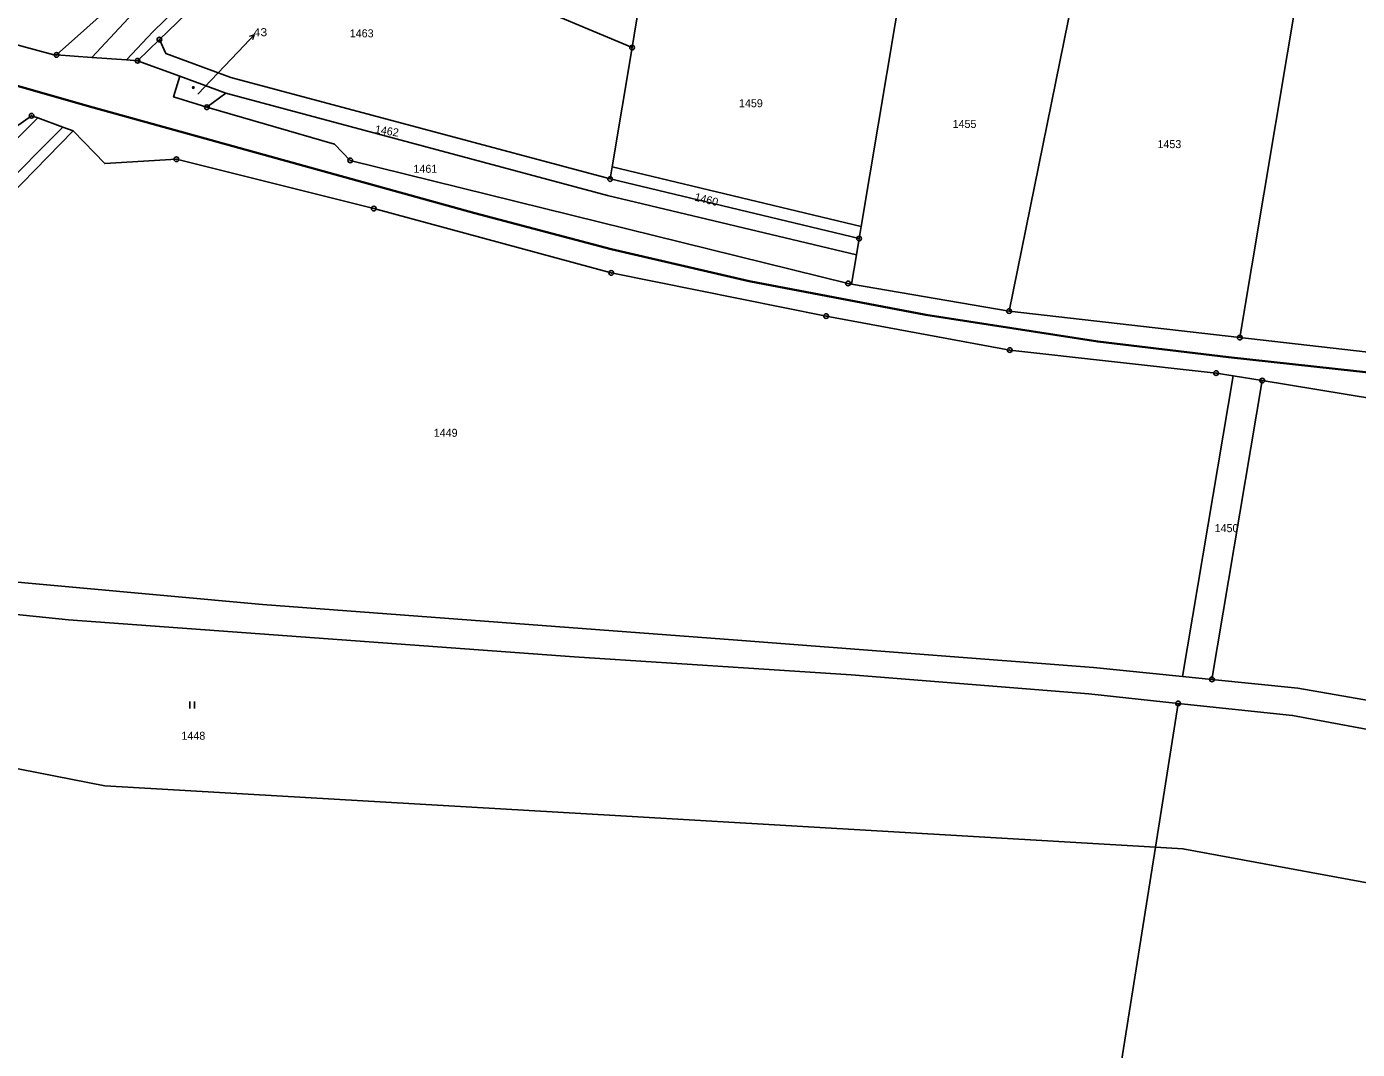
# Model space of a CAD drawing. Extents: x -872229 to -869198, y -1075981 to -1074329.
# Drawn here: x -871207 to -870924.3, y -1075586.7 to -1075369.5 of the extents above; entities that cross this region are included whole.
import ezdxf
from ezdxf.enums import TextEntityAlignment as Align

# ---------------------------------------------------------------- set-up
doc = ezdxf.new("R2010")
doc.units = 0
doc.header["$LTSCALE"] = 0.68
for name, color, linetype, lineweight in [('1', 7, 'Continuous', 25), ('3', 7, 'Continuous', 25), ('4', 7, 'Continuous', 13), ('5', 7, 'Continuous', 25), ('6', 7, 'Continuous', 25), ('7', 7, 'Continuous', 13), ('8', 7, 'Continuous', 25)]:
    doc.layers.add(name, color=color, linetype=linetype, lineweight=lineweight)
doc.layers.add('2', color=7, linetype='Continuous')

msp = doc.modelspace()

# ---------------------------------------------------------------- linework, layer by layer
at = {"layer": '1'}
for p, q in [((-871149.52, -1075343.97), (-871178.79, -1075372.22)), ((-871078.37, -1075373.89), (-871149.52, -1075343.97)), ((-871183.42, -1075376.69), (-871174.48, -1075379.98))]:
    msp.add_line(p, q, dxfattribs=at)
for points in [[(-871146.74, -1075326.85), (-871149.26, -1075329.47), (-871152.59, -1075332.45), (-871180.67, -1075357.59), (-871200.62, -1075375.46)], [(-870928.54, -1075345.19), (-870929.33, -1075345.1), (-870934.07, -1075344.52), (-870949.31, -1075435.5)], [(-871074.84, -1075352.78), (-871077.5, -1075368.64), (-871078.37, -1075373.89), (-871082.62, -1075399.25), (-871029.72, -1075411.9)], [(-870984.86, -1075363.6), (-871020.66, -1075357.83), (-871029.72, -1075411.9), (-871030.15, -1075414.48), (-871030.73, -1075417.93), (-871031.77, -1075424.14), (-870998.3, -1075429.88)], [(-871243.8, -1075363.33), (-871207.98, -1075373.63), (-871201.2, -1075375.48), (-871200.62, -1075375.46)], [(-870984.86, -1075363.6), (-870998.3, -1075429.88), (-870949.31, -1075435.5)], [(-871083.05, -1075401.82), (-871163.59, -1075380.25), (-871177.43, -1075375.17), (-871178.79, -1075372.22), (-871183.42, -1075376.69)], [(-871200.62, -1075375.46), (-871193.17, -1075376.03), (-871185.81, -1075376.53), (-871183.42, -1075376.69)], [(-871030.73, -1075417.93), (-871083.63, -1075405.29), (-871164.66, -1075383.59)], [(-871168.71, -1075386.58), (-871141.62, -1075394.43), (-871138.24, -1075397.87), (-871032.51, -1075424.01), (-871031.77, -1075424.14)], [(-871197.08, -1075391.62), (-871199.28, -1075390.81), (-871204.62, -1075388.86), (-871205.94, -1075388.38), (-871212.24, -1075392.84)], [(-871197.08, -1075391.62), (-871246.11, -1075441.8), (-871278.54, -1075475.47)], [(-870950.68, -1075443.64), (-870954.33, -1075443.04), (-870998.17, -1075438.16), (-871037.17, -1075430.94), (-871082.81, -1075421.77), (-871133.25, -1075408.1), (-871175.19, -1075397.63), (-871190.41, -1075398.53), (-871197.08, -1075391.62)], [(-871082.62, -1075399.25), (-871083.05, -1075401.82), (-871030.15, -1075414.48)], [(-870949.31, -1075435.5), (-870912.76, -1075439.69), (-870824.05, -1075448.17), (-870816.69, -1075448.69), (-870813.04, -1075448.95), (-870783.54, -1075451.03), (-870689.55, -1075462.28), (-870596.02, -1075472.9), (-870575.95, -1075474.7)], [(-871278.54, -1075475.47), (-871235.98, -1075483.88), (-871218.31, -1075486.6), (-871156.9, -1075492.22), (-871055.97, -1075499.77), (-870980.4, -1075505.56), (-870961.43, -1075507.47), (-870950.68, -1075443.64)], [(-870961.43, -1075507.47), (-870955.2, -1075508.1), (-870944.51, -1075444.65), (-870950.68, -1075443.64)], [(-870817.87, -1075462.75), (-870872.87, -1075452.61), (-870914.84, -1075449.51), (-870944.51, -1075444.65)], [(-870962.39, -1075513.2), (-870981.34, -1075511.21), (-871031.87, -1075507.16), (-871090.68, -1075503.32), (-871198.07, -1075495.44), (-871222.24, -1075493), (-871248.51, -1075487.96), (-871283.35, -1075480.46)], [(-870967.23, -1075543.73), (-871082, -1075537.03), (-871190.36, -1075530.7), (-871309.29, -1075507.4)], [(-870955.2, -1075508.1), (-870936.99, -1075509.94), (-870905.68, -1075515.44), (-870845.51, -1075527.2), (-870825.33, -1075530.87)], [(-870769.48, -1075546.88), (-870771.86, -1075546.41), (-870820.28, -1075537.54), (-870823.66, -1075536.9), (-870849.48, -1075531.79), (-870906.42, -1075521.68), (-870938.07, -1075515.76), (-870962.39, -1075513.2), (-870967.23, -1075543.73)], [(-870967.23, -1075543.73), (-870990.41, -1075689.92), (-871013.78, -1075837.33)], [(-870775.56, -1075578.36), (-870961.39, -1075544.07), (-870967.23, -1075543.73)]]:
    msp.add_lwpolyline(points, dxfattribs=at)
msp.add_lwpolyline([(-871174.48, -1075379.98), (-871175.76, -1075384.38), (-871168.71, -1075386.58), (-871164.66, -1075383.59)], close=True, dxfattribs=at)
at = {"layer": '3'}
for p, q in [((-871172.351, -1075514.29), (-871172.351, -1075512.79)), ((-871171.35, -1075514.29), (-871171.35, -1075512.79))]:
    msp.add_line(p, q, dxfattribs=at)
at = {"layer": '4'}
for p, q in [((-871180.16, -1075370.54), (-871118.25, -1075310.04)), ((-871185.81, -1075376.53), (-871180.16, -1075370.54)), ((-871199.28, -1075390.81), (-871239.07, -1075430.66))]:
    msp.add_line(p, q, dxfattribs=at)
for points in [[(-871144.78, -1075328.38), (-871161.44, -1075344.27), (-871180.53, -1075362.44), (-871193.17, -1075376.03)], [(-871326.72, -1075514.76), (-871291.4, -1075477.73), (-871251.44, -1075435.93), (-871204.62, -1075388.86)]]:
    msp.add_lwpolyline(points, dxfattribs=at)
at = {"layer": '5'}
msp.add_circle((-871171.5668, -1075382.3992), 0.175, dxfattribs=at)
at = {"layer": '6', "lineweight": 35}
for p, q in [((-871192.83, -1075386.61), (-871111.78, -1075409.09)), ((-871053.48, -1075423.53), (-871015.95, -1075430.68))]:
    msp.add_line(p, q, dxfattribs=at)
for points in [[(-871283.38, -1075360.82), (-871232.19, -1075375.42), (-871192.83, -1075386.61)], [(-871111.78, -1075409.09), (-871082.8, -1075416.75), (-871053.48, -1075423.53)], [(-871015.95, -1075430.68), (-870979.48, -1075436.37), (-870951.66, -1075439.69), (-870910.94, -1075444.16)]]:
    msp.add_lwpolyline(points, dxfattribs=at)
at = {"layer": '7'}
msp.add_line((-871158.683, -1075371.165), (-871159.733, -1075371.556), dxfattribs=at)
msp.add_lwpolyline([(-871170.66, -1075383.82), (-871160.73, -1075373.36), (-871158.683, -1075371.165), (-871159, -1075372.239)], dxfattribs=at)
at = {"layer": '8'}
for centre, radius in [((-871178.79, -1075372.2199), 0.5), ((-871178.79, -1075372.2199), 0.0303), ((-871078.37, -1075373.8899), 0.5), ((-871078.37, -1075373.8899), 0.0303), ((-871200.62, -1075375.4599), 0.5), ((-871200.62, -1075375.4599), 0.0303), ((-871183.42, -1075376.6899), 0.5), ((-871183.42, -1075376.6899), 0.0303), ((-871205.94, -1075388.3799), 0.5), ((-871168.71, -1075386.5799), 0.5), ((-871168.71, -1075386.5799), 0.0303), ((-871205.94, -1075388.3799), 0.0303), ((-871175.19, -1075397.6299), 0.5), ((-871175.19, -1075397.6299), 0.0303), ((-871138.24, -1075397.8699), 0.5), ((-871138.24, -1075397.8699), 0.0303), ((-871083.05, -1075401.8199), 0.5), ((-871083.05, -1075401.8199), 0.0303), ((-871133.25, -1075408.0999), 0.5), ((-871133.25, -1075408.0999), 0.0303), ((-871030.15, -1075414.4799), 0.5), ((-871030.15, -1075414.4799), 0.0303), ((-871082.81, -1075421.7699), 0.5), ((-871082.81, -1075421.7699), 0.0303), ((-871032.51, -1075424.0099), 0.5), ((-871032.51, -1075424.0099), 0.0303), ((-871037.17, -1075430.9399), 0.5), ((-870998.3, -1075429.8799), 0.5), ((-870998.3, -1075429.8799), 0.0303), ((-871037.17, -1075430.9399), 0.0303), ((-870949.31, -1075435.4999), 0.5), ((-870949.31, -1075435.4999), 0.0303), ((-870998.17, -1075438.1599), 0.5), ((-870998.17, -1075438.1599), 0.0303), ((-870954.33, -1075443.0399), 0.5), ((-870954.33, -1075443.0399), 0.0303), ((-870944.51, -1075444.6499), 0.5), ((-870944.51, -1075444.6499), 0.0303), ((-870955.2, -1075508.0999), 0.5), ((-870955.2, -1075508.0999), 0.0303), ((-870962.39, -1075513.1999), 0.5), ((-870962.39, -1075513.1999), 0.0303)]:
    msp.add_circle(centre, radius, dxfattribs=at)

# ---------------------------------------------------------------- texts
at = {"layer": '2', "width": 1.15}
msp.add_text('43', height=1.7, dxfattribs=at).set_placement((-871157.34, -1075371.49), align=Align.CENTER)
at = {"layer": '2'}
for s, p in [('1463', (-871138.35, -1075371.73)), ('1459', (-871055.67, -1075386.58)), ('1455', (-871010.3, -1075390.98)), ('1453', (-870966.78, -1075395.26)), ('1461', (-871124.82, -1075400.51)), ('1449', (-871120.51, -1075456.58)), ('1450', (-870954.64, -1075476.83)), ('1448', (-871174.11, -1075520.93))]:
    msp.add_text(s, height=1.7, dxfattribs=at).set_placement(p)
for s, rotation, p in [('1462', 351, (-871133.092, -1075392.049)), ('1460', 346, (-871065.245, -1075406.384))]:
    msp.add_text(s, height=1.7, rotation=rotation, dxfattribs=at).set_placement(p)

doc.saveas('drawing.dxf')
